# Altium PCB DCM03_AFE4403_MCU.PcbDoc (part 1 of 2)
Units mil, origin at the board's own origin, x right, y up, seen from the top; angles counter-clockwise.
Board outline 608.6 x 413.33 mil, 6 copper layers (Top Layer, Mid-Layer 1, Mid-Layer 2, Mid-Layer 3, Mid-Layer 4, Bottom Layer); 22 components, 39 nets, 207 pads, 99 vias.
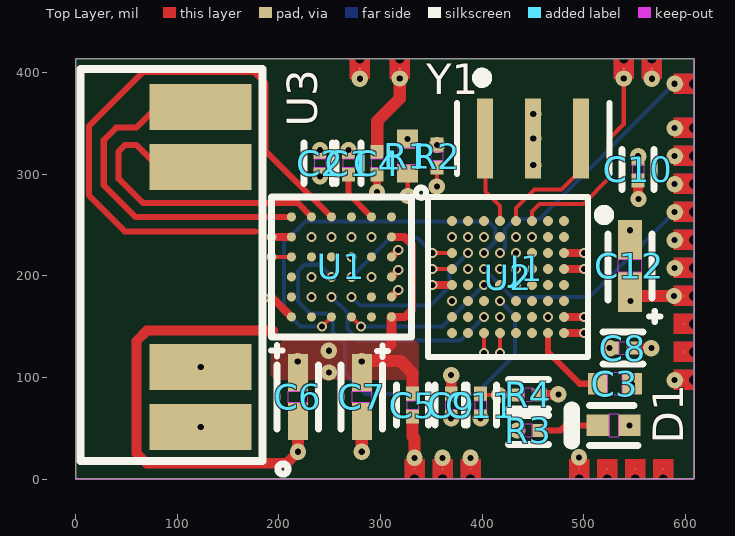
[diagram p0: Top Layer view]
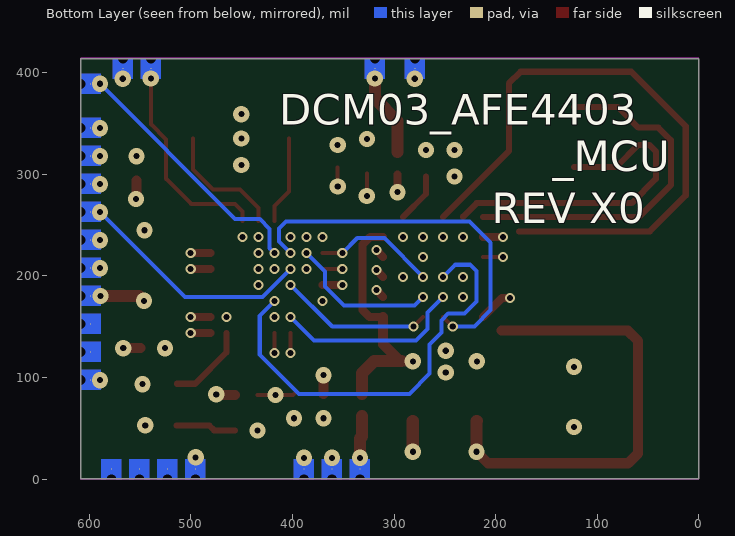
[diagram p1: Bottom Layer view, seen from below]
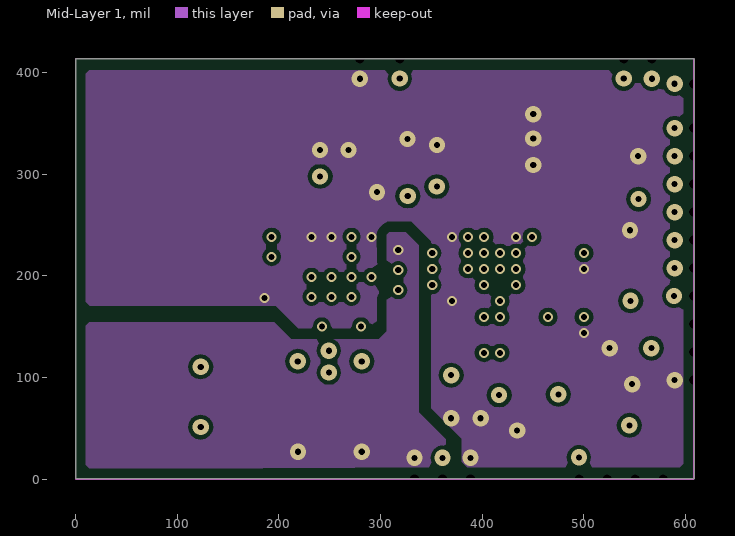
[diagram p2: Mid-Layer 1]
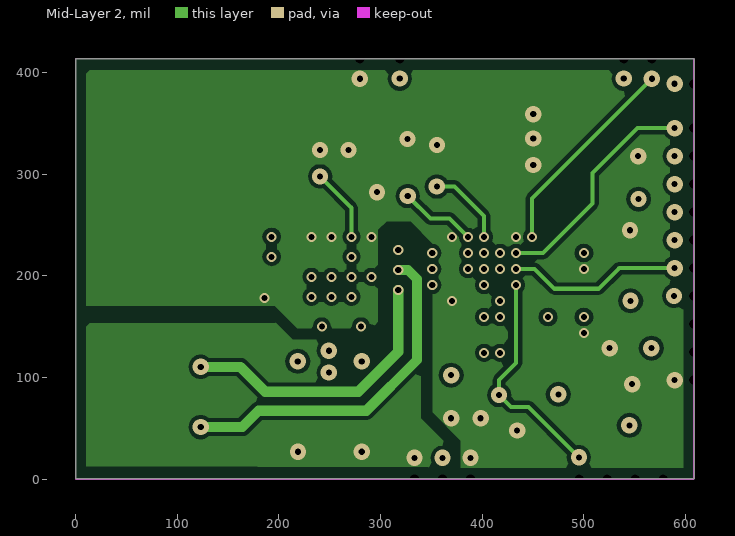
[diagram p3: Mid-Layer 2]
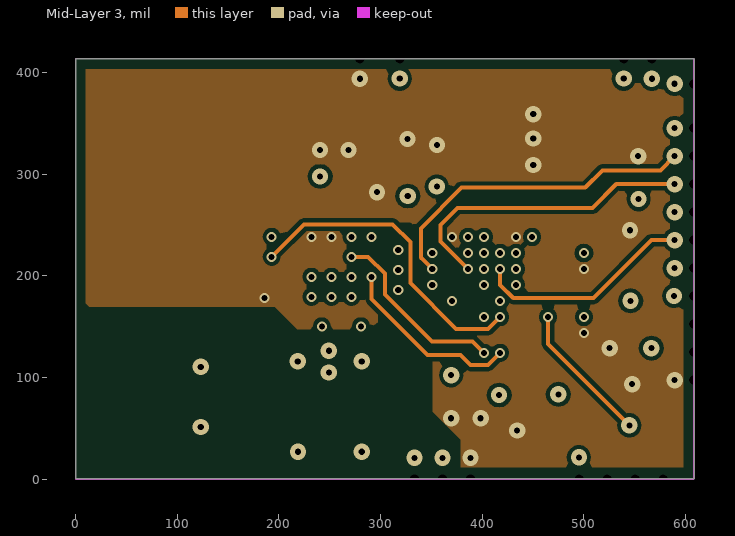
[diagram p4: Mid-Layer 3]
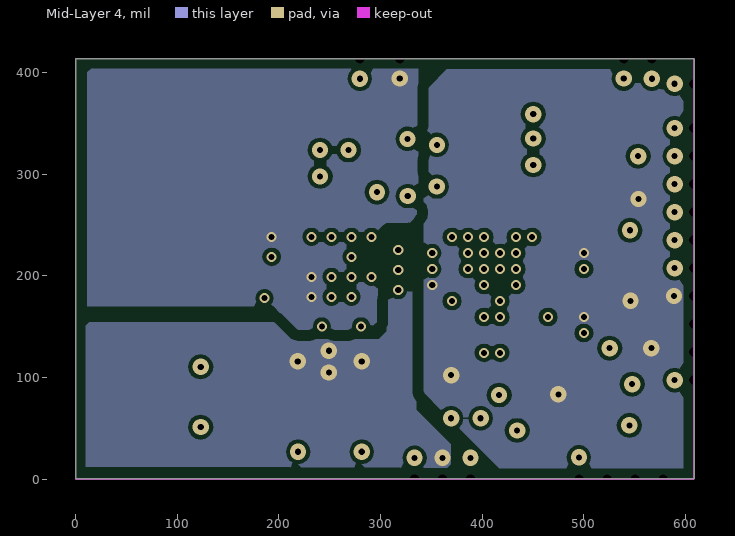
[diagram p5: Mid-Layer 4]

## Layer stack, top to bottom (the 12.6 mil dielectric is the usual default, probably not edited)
Top Layer: signal copper 1.4
Dielectric: dielectric 12.6, FR-4, Dk 4.8
Mid-Layer 1: signal copper 1.4
Dielectric: dielectric 12.6, FR-4, Dk 4.8
Mid-Layer 2: signal copper 1.4
Dielectric: dielectric 12.6, FR-4, Dk 4.8
Mid-Layer 3: signal copper 1.4
Dielectric: dielectric 12.6, FR-4, Dk 4.8
Mid-Layer 4: signal copper 1.4
Dielectric: dielectric 12.6, FR-4, Dk 4.8
Bottom Layer: signal copper 1.4

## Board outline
0,0.62 0,413.95 608.6,413.95 608.6,0.62

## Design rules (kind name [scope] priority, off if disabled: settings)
AcuteAngle [All] p1: minimum=4.50000000000000E+0001 checktracksonly=FALSE
AssemblyTestPointUsage [All] p1: valid=2
Clearance Clearance_1 [inpoly vs inpoly] p1: gap=10
Clearance [All] p2: gap=4
Clearance Clearance_Poly [InPolygon] p3: gap=8
ComponentClearance ComponentClearance_Logo [InComponentClass('Logo')] p1: gap=50 collisioncheckmode=3 verticalgap=10 showdistances=FALSE
ComponentClearance ComponentClearance_ScrewToNut [(HasFootprint('NY PMS 440 0025 PH')) vs (HasFootprint('Keystone_1902C'))] p2: gap=5 collisioncheckmode=3 verticalgap=10 showdistances=FALSE
ComponentClearance ComponentClearance_MountingHoles [InComponentClass('Mounting Holes')] p3: gap=250 collisioncheckmode=3 verticalgap=100000 showdistances=FALSE
ComponentClearance ComponentClearance_SmallPassives [HasFootprint('0201*') or HasFootprint('0402*') or HasFootprint('0508') or HasFootprint('0603*') or HasFootprint('0612') or HasFootprint('0805*') or HasFootprint('0815*') or HasFootprint('0830*') or HasFootprint('1206*') or HasFootprint('1210*') or HasFootprint('1808*') or HasFootprint('1812*') or HasFootprint('1825*') or HasFootprint('2010*') or HasFootprint('2220*') or HasFootprint('2225*') or HasFootprint('2512*') or HasFootprint('2728*') or HasFootprint('3518*') vs HasFootprint('0201*') or HasFootprint('0402*') or HasFootprint('0508') or HasFootprint('0603*') or HasFootprint('0612') or HasFootprint('0805*') or HasFootprint('0815*') or HasFootprint('0830*') or HasFootprint('1206*') or HasFootprint('1210*') or HasFootprint('1808*') or HasFootprint('1812*') or HasFootprint('1825*') or HasFootprint('2010*') or HasFootprint('2220*') or HasFootprint('2225*') or HasFootprint('2512*') or HasFootprint('2728*') or HasFootprint('3518*')] p4: gap=20 collisioncheckmode=3 verticalgap=10 showdistances=FALSE
ComponentClearance ComponentClearance_THtoSMT [IsThruComponent vs IsSMTComponent] p5: gap=100 collisioncheckmode=3 verticalgap=30 showdistances=FALSE
ComponentClearance ComponentClearance_THtoTH [IsThruComponent vs IsThruComponent] p6: gap=118.11 collisioncheckmode=3 verticalgap=30 showdistances=FALSE
ComponentClearance [All] p7: gap=40 collisioncheckmode=3 verticalgap=10 showdistances=FALSE
DiffPairsRouting [All] p1: maxlimit=100 minlimit=10 mostfreqgap=10 maxuncoupledlength=1000
FabricationTestPointUsage TestPointUsage [All] p1: valid=2 allowmultiple=FALSE
FabricationTestpoint Testpoint [All] p1: side=3 testpointundercomponent=TRUE minsize=40 maxsize=100 preferedsize=60 minholesize=0 maxholesize=40 preferedholesize=32 testpointgrid=1 allowsidetop=TRUE allowsidebottom=TRUE usegrid=TRUE gridtolerance=0.01
FanoutControl Fanout_LCC [IsLCC] p1: bgadir=Out bgaviamode=Centered fanoutstyle=Auto fanoutdirection=Alternating viagrid=1 // Fanout_LCC (Default Rule)
FanoutControl Fanout_BGA [IsBGA] p2: bgadir=Out bgaviamode=Centered fanoutstyle=Auto fanoutdirection=Alternating viagrid=1 // Fanout_BGA (Default Rule)
FanoutControl Fanout_Default [All] p4: bgadir=Out bgaviamode=Centered fanoutstyle=Auto fanoutdirection=Alternating viagrid=1 // Fanout_Default (Default Rule)
FanoutControl Fanout_Small [(CompPinCount < 5)] p5: bgadir=Out bgaviamode=Centered fanoutstyle=Auto fanoutdirection=OutThenIn viagrid=1 // Fanout_Small (Default Rule)
HoleSize [All] p1: absolutevalues=TRUE maxlimit=251 minlimit=8 maxpercent=80.000 minpercent=20.000
HoleToHoleClearance [All] p1: gap=9.75 allowstackedmicrovias=TRUE
MinimumAnnularRing MinimumAnnularRing_ThermalPadVias [IsVia and InAnyComponent] p1: minimumring=5.91
MinimumAnnularRing [All] p2: minimumring=9
MinimumSolderMaskSliver MinimumSolderMaskSliver_Logo [InComponentClass('Logo') vs InComponentClass('Logo')] p1: minsoldermaskwidth=0.7
MinimumSolderMaskSliver [All] p2: minsoldermaskwidth=3.94
PlaneClearance [All] p1: clearance=15
PlaneConnect PlaneConnect_1 [isvia] p1: planeconnectstyle=Direct reliefexpansion=20 reliefentries=4 reliefconductorwidth=10 reliefairgap=10
PlaneConnect [All] p2: planeconnectstyle=Relief reliefexpansion=10 reliefentries=4 reliefconductorwidth=10 reliefairgap=10
PolygonConnect [All] p1: connectstyle=Direct reliefconductorwidth=10 reliefentries=4 polygonreliefangle="90 Angle"
RoutingVias ThermalPadVias [IsVia and InAnyComponent] p1: holewidth=7.87 width=19.68 viastyle="Through Hole" minholewidth=7.87 minwidth=19.68 maxholewidth=12.99 maxwidth=23.62
RoutingVias [All] p2: holewidth=16 width=34 viastyle="Through Hole" minholewidth=7.87 minwidth=26 maxholewidth=40 maxwidth=65
SMDToCorner [All] p1: distance=30000
SilkToSilkClearance [All] p1: silktosilkclearance=5
SilkscreenOverComponentPads [All] p1: minsilkscreentomaskgap=5
SolderMaskExpansion [All] p1: expansion=0
Width [All] p1: maxlimit=100 minlimit=4 preferedwidth=10 checkconnectedcopper=TRUE
12 further rules are at their usual default settings.

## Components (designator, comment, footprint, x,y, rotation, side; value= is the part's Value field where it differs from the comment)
C1 "CL03A104KP3NNNC" 0201 268.6,310.95 r90 top locked
C2 "CL03A104KP3NNNC" 0201 240.6,310.95 r90 top locked
C3 "#NAME?" 0402 530.6,93.95 r0 top
C4 "CL03A104KP3NNNC" 0201 296.6,310.95 r270 top locked
C5 "CL03A104KP3NNNC" 0201 331.6,72.95 r270 top locked
C6 "#NAME?" C0603_POL 218.6,80.95 r270 top
C7 "#NAME?" C0603_POL 281.6,80.95 r270 top locked
C8 "CL03A104KP3NNNC" 0201 538.6,128.95 r180 top locked
C9 "CL03A104KP3NNNC" 0201 369.6,72.95 r270 top locked
C10 "CL03A104KP3NNNC" 0201 553.6,304.95 r90 top locked
C11 "GRM033R61A222KA01D" 0201 398.6,72.95 r270 top locked
C12 "#NAME?" C0603_POL1 545.6,209.95 r90 top locked
D1 "PartNumber" LED_0402 529.6,52.95 r0 top locked
J1 "22pin SPO2 Module Connector" CONN-22PADS 608.59,-5.05 r270 top locked
R1 "CRCW04021M00JNED" R0402 326.6,317.95 r270 top
R2 "ERJ-1GE0R00C" R0201 355.6,317.95 r90 top
R3 "RC0603F332CS" R0201 445.6,47.95 r0 top locked
R4 "RC0603F473CS" R0201 445.6,82.95 r0 top locked
U1 "AFE4403" BGA36C50P6X6_304X304X50 261.6,208.95 r270 top locked
U2 "PartNumber" YFF-64 425.6,198.95 r180 top locked
U3 "#NAME?" DCM03 89.6,210.95 r90 top locked
Y1 "PartNumber" RESONATOR-1.3X3.2-MURATA 450.37,335.23 r0 top locked

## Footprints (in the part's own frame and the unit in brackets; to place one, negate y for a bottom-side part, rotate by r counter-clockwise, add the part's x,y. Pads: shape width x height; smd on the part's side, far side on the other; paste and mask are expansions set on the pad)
0201 [mm] "CAP, 0201, 2-PIN"
  rect 0.36x0.32 smd: 1(-0.28,0) 2(0.28,0)
  Top Layer keep-out region: -0.1,-0.15 0.1,-0.15 0.1,0.15 -0.1,0.15
  silkscreen extent -0.5,0.4 0.5,0.4, body extent -0.3,-0.15 0.3,0.15, height 0.33
0402 [mm] "CAP, 0402, 2-PIN"
  rect 0.49x0.54 smd: 1(-0.43,0) 2(0.43,0)
  Top Layer keep-out region: -0.19,-0.27 0.19,-0.27 0.19,0.27 -0.19,0.27
  body extent -0.5,-0.25 0.5,0.25, height 0.56
BGA36C50P6X6_304X304X50 [mm] "BGA, 0.5mm pitch, 6X6, 36 pins"
  round 0.23 smd: A1(-1.25,1.25) A2(-0.75,1.25) A3(-0.25,1.25) A4(0.25,1.25) A5(0.75,1.25) A6(1.25,1.25) B1(-1.25,0.75) B2(-0.75,0.75) B3(-0.25,0.75) B4(0.25,0.75) B5(0.75,0.75) B6(1.25,0.75) C1(-1.25,0.25) C2(-0.75,0.25) C3(-0.25,0.25) C4(0.25,0.25) C5(0.75,0.25) C6(1.25,0.25) D1(-1.25,-0.25) D2(-0.75,-0.25) D3(-0.25,-0.25) D4(0.25,-0.25) D5(0.75,-0.25) D6(1.25,-0.25) E1(-1.25,-0.75) E2(-0.75,-0.75) E3(-0.25,-0.75) E4(0.25,-0.75) E5(0.75,-0.75) E6(1.25,-0.75) F1(-1.25,-1.25) F2(-0.75,-1.25) F3(-0.25,-1.25) F4(0.25,-1.25) F5(0.75,-1.25) F6(1.25,-1.25)
  silkscreen extent -1.98,-1.75 1.75,2.12, body extent -1.52,-1.52 1.52,1.52, height 0.5
C0603_POL [mm] "CAP, TANTALUM, 2-PIN"
  rect 0.95x0.5 smd: 1(-0.6,0) 2(0.6,0)
  Top Layer keep-out region: -0.13,-0.25 0.13,-0.25 0.13,0.25 -0.13,0.25
  silkscreen extent -0.8,-0.52 0.8,0.52, body extent -0.8,-0.43 0.8,0.43, height 0.9
C0603_POL1 [mm] "CAP, TANTULUM, 2-PIN"
  rect 1x0.6 smd: 1(-0.65,0) 2(0.65,0)
  Top Layer keep-out region: -0.15,-0.3 0.15,-0.3 0.15,0.3 -0.15,0.3
  silkscreen extent -0.85,-0.55 0.8,0.55, body extent -0.82,-0.45 0.82,0.45, height 0.9
CONN-22PADS [mil]
  round 0 hole 9.69 mask+0: 0(-419,-69.15) 0(-419,-41.59) 0(-419,-328.99) 0(-419,-289.62) 0(-394.11,0) 0(-350.76,0) 0(-323.2,0) 0(-295.64,0) 0(-268.08,0) 0(-240.52,0) 0(-212.96,0) 0(-185.4,0) 0(-157.84,0) 0(-130.29,0) 0(-102.73,0) 0(-5.01,-30.31) 0(-5.01,-57.87) 0(-5.01,-85.43) 0(-5.01,-112.99) 0(-5.01,-219.87) 0(-5.01,-247.43) 0(-5.01,-274.99)
  rect 1x1 smd: 1(-409.16,-289.62) 2(-409.16,-328.99) 3(-130.28,-9.84) 4(-157.84,-9.84) 5(-14.85,-57.87) 6(-240.52,-9.84) 7(-295.64,-9.84) 8(-323.2,-9.84) 9(-268.08,-9.84) 10(-102.72,-9.84) 11(-14.85,-85.43) 12(-14.85,-30.31) 13(-14.85,-274.99) 14(-14.85,-247.43) 15(-350.76,-9.84) 16(-409.16,-69.15) 17(-14.85,-112.99) 18(-212.96,-9.84) 19(-409.16,-41.59) 20(-394.11,-9.84) 21(-185.4,-9.84) 22(-14.85,-219.87)
  rect 1x1 smd far side: 1(-409.16,-289.62) 2(-409.16,-328.99) 3(-130.28,-9.84) 4(-157.84,-9.84) 5(-14.85,-57.87) 6(-240.52,-9.84) 7(-295.64,-9.84) 8(-323.2,-9.84) 9(-268.08,-9.84) 10(-102.72,-9.84) 11(-14.85,-85.43) 12(-14.85,-30.31) 13(-14.85,-274.99) 14(-14.85,-247.43) 15(-350.76,-9.84) 16(-409.16,-69.15) 17(-14.85,-112.99) 18(-212.96,-9.84) 19(-409.16,-41.59) 20(-394.11,-9.84) 21(-185.4,-9.84) 22(-14.85,-219.87)
  Top Layer region: -5.01,-279.83 -5.01,-284.83 -24.69,-284.83 -24.69,-265.14 -5.01,-265.14 -5.01,-270.14 -5.58,-270.22 -6.23,-270.46 -7.02,-270.83 -7.69,-271.34 -8.28,-271.93 -8.74,-272.68 -9.1,-273.53 -9.27,-274.27 -9.33,-275.1 -9.25,-275.8 -9.09,-276.52 -8.63,-277.48 -8.11,-278.2 -7.4,-278.82 -6.78,-279.19 -6.25,-279.48 -5.71,-279.68 -5.01,-279.83
  Top Layer region: -5.01,-252.27 -5.01,-257.27 -24.69,-257.27 -24.69,-237.59 -5.01,-237.59 -5.01,-242.59 -5.58,-242.66 -6.23,-242.9 -7.02,-243.27 -7.69,-243.78 -8.28,-244.38 -8.74,-245.12 -9.1,-245.97 -9.27,-246.71 -9.33,-247.54 -9.25,-248.24 -9.09,-248.96 -8.63,-249.92 -8.11,-250.64 -7.4,-251.26 -6.78,-251.64 -6.25,-251.92 -5.71,-252.12 -5.01,-252.27
  Top Layer region: -5.01,-224.71 -5.01,-229.71 -24.69,-229.71 -24.69,-210.03 -5.01,-210.03 -5.01,-215.03 -5.58,-215.1 -6.23,-215.34 -7.02,-215.72 -7.69,-216.22 -8.28,-216.82 -8.74,-217.56 -9.1,-218.41 -9.27,-219.15 -9.33,-219.99 -9.25,-220.68 -9.09,-221.4 -8.63,-222.36 -8.11,-223.08 -7.4,-223.7 -6.78,-224.08 -6.25,-224.37 -5.71,-224.56 -5.01,-224.71
  Top Layer region: -5.01,-117.83 -5.01,-122.83 -24.69,-122.83 -24.69,-103.14 -5.01,-103.14 -5.01,-108.14 -5.58,-108.22 -6.23,-108.46 -7.02,-108.83 -7.69,-109.34 -8.28,-109.93 -8.74,-110.68 -9.1,-111.53 -9.27,-112.27 -9.33,-113.1 -9.25,-113.8 -9.09,-114.52 -8.63,-115.48 -8.11,-116.2 -7.4,-116.82 -6.78,-117.19 -6.25,-117.48 -5.71,-117.68 -5.01,-117.83
  Top Layer region: -5.01,-90.27 -5.01,-95.27 -24.69,-95.27 -24.69,-75.59 -5.01,-75.59 -5.01,-80.59 -5.58,-80.66 -6.23,-80.9 -7.02,-81.27 -7.69,-81.78 -8.28,-82.38 -8.74,-83.12 -9.1,-83.97 -9.27,-84.71 -9.33,-85.54 -9.25,-86.24 -9.09,-86.96 -8.63,-87.92 -8.11,-88.64 -7.4,-89.26 -6.78,-89.64 -6.25,-89.92 -5.71,-90.12 -5.01,-90.27
  Top Layer region: -5.01,-62.71 -5.01,-67.71 -24.69,-67.71 -24.69,-48.03 -5.01,-48.03 -5.01,-53.03 -5.58,-53.1 -6.23,-53.34 -7.02,-53.72 -7.69,-54.22 -8.28,-54.82 -8.74,-55.56 -9.1,-56.41 -9.27,-57.15 -9.33,-57.99 -9.25,-58.68 -9.09,-59.4 -8.63,-60.36 -8.11,-61.08 -7.4,-61.7 -6.78,-62.08 -6.25,-62.37 -5.71,-62.56 -5.01,-62.71
  Top Layer region: -5.01,-35.15 -5.01,-40.15 -24.69,-40.15 -24.69,-20.47 -5.01,-20.47 -5.01,-25.47 -5.58,-25.55 -6.23,-25.78 -7.02,-26.16 -7.69,-26.66 -8.28,-27.26 -8.74,-28 -9.1,-28.85 -9.27,-29.59 -9.33,-30.43 -9.25,-31.12 -9.09,-31.84 -8.63,-32.8 -8.11,-33.52 -7.4,-34.14 -6.78,-34.52 -6.25,-34.81 -5.71,-35 -5.01,-35.15
  Top Layer region: -97.88,0 -92.88,0 -92.88,-19.68 -112.57,-19.68 -112.57,0 -107.57,0 -107.49,-0.57 -107.26,-1.22 -106.88,-2.01 -106.38,-2.68 -105.78,-3.27 -105.04,-3.73 -104.19,-4.09 -103.44,-4.26 -102.61,-4.32 -101.92,-4.24 -101.2,-4.08 -100.23,-3.62 -99.52,-3.1 -98.9,-2.39 -98.52,-1.77 -98.23,-1.24 -98.03,-0.7 -97.89,0
  Top Layer region: -125.44,0 -120.44,0 -120.44,-19.68 -140.13,-19.68 -140.13,0 -135.13,0 -135.05,-0.57 -134.82,-1.22 -134.44,-2.01 -133.94,-2.68 -133.34,-3.27 -132.59,-3.73 -131.74,-4.09 -131,-4.26 -130.17,-4.32 -129.48,-4.24 -128.76,-4.08 -127.79,-3.62 -127.08,-3.1 -126.46,-2.39 -126.08,-1.77 -125.79,-1.24 -125.59,-0.7 -125.45,0
  Top Layer region: -153,0 -148,0 -148,-19.68 -167.69,-19.68 -167.69,0 -162.69,0 -162.61,-0.57 -162.38,-1.22 -162,-2.01 -161.5,-2.68 -160.9,-3.27 -160.15,-3.73 -159.3,-4.09 -158.56,-4.26 -157.73,-4.32 -157.04,-4.24 -156.32,-4.08 -155.35,-3.62 -154.64,-3.1 -154.02,-2.39 -153.64,-1.77 -153.35,-1.24 -153.15,-0.7 -153.01,0
  Top Layer region: -180.56,0 -175.56,0 -175.56,-19.68 -195.25,-19.68 -195.25,0 -190.25,0 -190.17,-0.57 -189.94,-1.22 -189.56,-2.01 -189.05,-2.68 -188.46,-3.27 -187.71,-3.73 -186.86,-4.09 -186.12,-4.26 -185.29,-4.32 -184.6,-4.24 -183.87,-4.08 -182.91,-3.62 -182.19,-3.1 -181.57,-2.39 -181.2,-1.77 -180.91,-1.24 -180.71,-0.7 -180.56,0
  Top Layer region: -208.12,0 -203.12,0 -203.12,-19.68 -222.81,-19.68 -222.81,0 -217.81,0 -217.73,-0.57 -217.49,-1.22 -217.12,-2.01 -216.61,-2.68 -216.02,-3.27 -215.27,-3.73 -214.42,-4.09 -213.68,-4.26 -212.85,-4.32 -212.15,-4.24 -211.43,-4.08 -210.47,-3.62 -209.75,-3.1 -209.13,-2.39 -208.76,-1.77 -208.47,-1.24 -208.27,-0.7 -208.12,0
  Top Layer region: -235.68,0 -230.68,0 -230.68,-19.68 -250.36,-19.68 -250.36,0 -245.36,0 -245.29,-0.57 -245.05,-1.22 -244.68,-2.01 -244.17,-2.68 -243.57,-3.27 -242.83,-3.73 -241.98,-4.09 -241.24,-4.26 -240.41,-4.32 -239.71,-4.24 -238.99,-4.08 -238.03,-3.62 -237.31,-3.1 -236.69,-2.39 -236.31,-1.77 -236.03,-1.24 -235.83,-0.7 -235.68,0
  Top Layer region: -263.24,0 -258.24,0 -258.24,-19.68 -277.92,-19.68 -277.92,0 -272.92,0 -272.85,-0.57 -272.61,-1.22 -272.23,-2.01 -271.73,-2.68 -271.13,-3.27 -270.39,-3.73 -269.54,-4.09 -268.8,-4.26 -267.96,-4.32 -267.27,-4.24 -266.55,-4.08 -265.59,-3.62 -264.87,-3.1 -264.25,-2.39 -263.87,-1.77 -263.58,-1.24 -263.39,-0.7 -263.24,0
  Top Layer region: -290.8,0 -285.8,0 -285.8,-19.68 -305.48,-19.68 -305.48,0 -300.48,0 -300.4,-0.57 -300.17,-1.22 -299.79,-2.01 -299.29,-2.68 -298.69,-3.27 -297.95,-3.73 -297.1,-4.09 -296.36,-4.26 -295.52,-4.32 -294.83,-4.24 -294.11,-4.08 -293.15,-3.62 -292.43,-3.1 -291.81,-2.39 -291.43,-1.77 -291.14,-1.24 -290.95,-0.7 -290.8,0
  Top Layer region: -318.36,0 -313.36,0 -313.36,-19.68 -333.04,-19.68 -333.04,0 -328.04,0 -327.96,-0.57 -327.73,-1.22 -327.35,-2.01 -326.85,-2.68 -326.25,-3.27 -325.51,-3.73 -324.66,-4.09 -323.92,-4.26 -323.08,-4.32 -322.39,-4.24 -321.67,-4.08 -320.71,-3.62 -319.99,-3.1 -319.37,-2.39 -318.99,-1.77 -318.7,-1.24 -318.51,-0.7 -318.36,0
  Top Layer region: -345.92,0 -340.92,0 -340.92,-19.68 -360.6,-19.68 -360.6,0 -355.6,0 -355.52,-0.57 -355.29,-1.22 -354.91,-2.01 -354.41,-2.68 -353.81,-3.27 -353.07,-3.73 -352.22,-4.09 -351.48,-4.26 -350.64,-4.32 -349.95,-4.24 -349.23,-4.08 -348.27,-3.62 -347.55,-3.1 -346.93,-2.39 -346.55,-1.77 -346.26,-1.24 -346.06,-0.7 -345.92,0
  Top Layer region: -389.27,0 -384.27,0 -384.27,-19.68 -403.96,-19.68 -403.96,0 -398.96,0 -398.88,-0.57 -398.64,-1.22 -398.27,-2.01 -397.76,-2.68 -397.17,-3.27 -396.42,-3.73 -395.57,-4.09 -394.83,-4.26 -394,-4.32 -393.3,-4.24 -392.58,-4.08 -391.62,-3.62 -390.9,-3.1 -390.28,-2.39 -389.91,-1.77 -389.62,-1.24 -389.42,-0.7 -389.27,0
  Top Layer region: -419,-36.75 -419,-31.75 -399.32,-31.75 -399.32,-51.43 -419,-51.43 -419,-46.43 -418.43,-46.35 -417.78,-46.12 -416.99,-45.74 -416.32,-45.24 -415.73,-44.64 -415.27,-43.9 -414.91,-43.05 -414.74,-42.31 -414.68,-41.47 -414.76,-40.78 -414.92,-40.06 -415.38,-39.1 -415.9,-38.38 -416.61,-37.76 -417.23,-37.38 -417.76,-37.09 -418.3,-36.9 -419,-36.75
  Top Layer region: -419,-64.31 -419,-59.31 -399.32,-59.31 -399.32,-78.99 -419,-78.99 -419,-73.99 -418.43,-73.91 -417.78,-73.68 -416.99,-73.3 -416.32,-72.8 -415.73,-72.2 -415.27,-71.46 -414.91,-70.61 -414.74,-69.87 -414.68,-69.03 -414.76,-68.34 -414.92,-67.62 -415.38,-66.66 -415.9,-65.94 -416.61,-65.32 -417.23,-64.94 -417.76,-64.65 -418.3,-64.46 -419,-64.31
  Top Layer region: -419,-284.78 -419,-279.78 -399.32,-279.78 -399.32,-299.46 -419,-299.46 -419,-294.46 -418.43,-294.39 -417.78,-294.15 -416.99,-293.78 -416.32,-293.27 -415.73,-292.67 -415.27,-291.93 -414.91,-291.08 -414.74,-290.34 -414.68,-289.51 -414.76,-288.81 -414.92,-288.09 -415.38,-287.13 -415.9,-286.41 -416.61,-285.79 -417.23,-285.41 -417.76,-285.13 -418.3,-284.93 -419,-284.78
  Top Layer region: -419,-324.15 -419,-319.15 -399.32,-319.15 -399.32,-338.83 -419,-338.83 -419,-333.83 -418.43,-333.76 -417.78,-333.52 -416.99,-333.15 -416.32,-332.64 -415.73,-332.04 -415.27,-331.3 -414.91,-330.45 -414.74,-329.71 -414.68,-328.88 -414.76,-328.18 -414.92,-327.46 -415.38,-326.5 -415.9,-325.78 -416.61,-325.16 -417.23,-324.78 -417.76,-324.5 -418.3,-324.3 -419,-324.15
  Bottom Layer region: -419,-324.15 -419,-319.15 -399.32,-319.15 -399.32,-338.83 -419,-338.83 -419,-333.83 -418.43,-333.76 -417.78,-333.52 -416.99,-333.15 -416.32,-332.64 -415.73,-332.04 -415.27,-331.3 -414.91,-330.45 -414.74,-329.71 -414.68,-328.88 -414.76,-328.18 -414.92,-327.46 -415.38,-326.5 -415.9,-325.78 -416.61,-325.16 -417.23,-324.78 -417.76,-324.5 -418.3,-324.3 -419,-324.15
  Bottom Layer region: -419,-284.78 -419,-279.78 -399.32,-279.78 -399.32,-299.46 -419,-299.46 -419,-294.46 -418.43,-294.39 -417.78,-294.15 -416.99,-293.78 -416.32,-293.27 -415.73,-292.67 -415.27,-291.93 -414.91,-291.08 -414.74,-290.34 -414.68,-289.51 -414.76,-288.81 -414.92,-288.09 -415.38,-287.13 -415.9,-286.41 -416.61,-285.79 -417.23,-285.41 -417.76,-285.13 -418.3,-284.93 -419,-284.78
  Bottom Layer region: -419,-64.31 -419,-59.31 -399.32,-59.31 -399.32,-78.99 -419,-78.99 -419,-73.99 -418.43,-73.91 -417.78,-73.68 -416.99,-73.3 -416.32,-72.8 -415.73,-72.2 -415.27,-71.46 -414.91,-70.61 -414.74,-69.87 -414.68,-69.03 -414.76,-68.34 -414.92,-67.62 -415.38,-66.66 -415.9,-65.94 -416.61,-65.32 -417.23,-64.94 -417.76,-64.65 -418.3,-64.46 -419,-64.31
  Bottom Layer region: -419,-36.75 -419,-31.75 -399.32,-31.75 -399.32,-51.43 -419,-51.43 -419,-46.43 -418.43,-46.35 -417.78,-46.12 -416.99,-45.74 -416.32,-45.24 -415.73,-44.64 -415.27,-43.9 -414.91,-43.05 -414.74,-42.31 -414.68,-41.47 -414.76,-40.78 -414.92,-40.06 -415.38,-39.1 -415.9,-38.38 -416.61,-37.76 -417.23,-37.38 -417.76,-37.09 -418.3,-36.9 -419,-36.75
  Bottom Layer region: -389.27,0 -384.27,0 -384.27,-19.68 -403.96,-19.68 -403.96,0 -398.96,0 -398.88,-0.57 -398.64,-1.22 -398.27,-2.01 -397.76,-2.68 -397.17,-3.27 -396.42,-3.73 -395.57,-4.09 -394.83,-4.26 -394,-4.32 -393.3,-4.24 -392.58,-4.08 -391.62,-3.62 -390.9,-3.1 -390.28,-2.39 -389.91,-1.77 -389.62,-1.24 -389.42,-0.7 -389.27,0
  Bottom Layer region: -345.92,0 -340.92,0 -340.92,-19.68 -360.6,-19.68 -360.6,0 -355.6,0 -355.52,-0.57 -355.29,-1.22 -354.91,-2.01 -354.41,-2.68 -353.81,-3.27 -353.07,-3.73 -352.22,-4.09 -351.48,-4.26 -350.64,-4.32 -349.95,-4.24 -349.23,-4.08 -348.27,-3.62 -347.55,-3.1 -346.93,-2.39 -346.55,-1.77 -346.26,-1.24 -346.06,-0.7 -345.92,0
  Bottom Layer region: -318.36,0 -313.36,0 -313.36,-19.68 -333.04,-19.68 -333.04,0 -328.04,0 -327.96,-0.57 -327.73,-1.22 -327.35,-2.01 -326.85,-2.68 -326.25,-3.27 -325.51,-3.73 -324.66,-4.09 -323.92,-4.26 -323.08,-4.32 -322.39,-4.24 -321.67,-4.08 -320.71,-3.62 -319.99,-3.1 -319.37,-2.39 -318.99,-1.77 -318.7,-1.24 -318.51,-0.7 -318.36,0
  Bottom Layer region: -290.8,0 -285.8,0 -285.8,-19.68 -305.48,-19.68 -305.48,0 -300.48,0 -300.4,-0.57 -300.17,-1.22 -299.79,-2.01 -299.29,-2.68 -298.69,-3.27 -297.95,-3.73 -297.1,-4.09 -296.36,-4.26 -295.52,-4.32 -294.83,-4.24 -294.11,-4.08 -293.15,-3.62 -292.43,-3.1 -291.81,-2.39 -291.43,-1.77 -291.14,-1.24 -290.95,-0.7 -290.8,0
  Bottom Layer region: -263.24,0 -258.24,0 -258.24,-19.68 -277.92,-19.68 -277.92,0 -272.92,0 -272.85,-0.57 -272.61,-1.22 -272.23,-2.01 -271.73,-2.68 -271.13,-3.27 -270.39,-3.73 -269.54,-4.09 -268.8,-4.26 -267.96,-4.32 -267.27,-4.24 -266.55,-4.08 -265.59,-3.62 -264.87,-3.1 -264.25,-2.39 -263.87,-1.77 -263.58,-1.24 -263.39,-0.7 -263.24,0
  Bottom Layer region: -235.68,0 -230.68,0 -230.68,-19.68 -250.36,-19.68 -250.36,0 -245.36,0 -245.29,-0.57 -245.05,-1.22 -244.68,-2.01 -244.17,-2.68 -243.57,-3.27 -242.83,-3.73 -241.98,-4.09 -241.24,-4.26 -240.41,-4.32 -239.71,-4.24 -238.99,-4.08 -238.03,-3.62 -237.31,-3.1 -236.69,-2.39 -236.31,-1.77 -236.03,-1.24 -235.83,-0.7 -235.68,0
  Bottom Layer region: -208.12,0 -203.12,0 -203.12,-19.68 -222.81,-19.68 -222.81,0 -217.81,0 -217.73,-0.57 -217.49,-1.22 -217.12,-2.01 -216.61,-2.68 -216.02,-3.27 -215.27,-3.73 -214.42,-4.09 -213.68,-4.26 -212.85,-4.32 -212.15,-4.24 -211.43,-4.08 -210.47,-3.62 -209.75,-3.1 -209.13,-2.39 -208.76,-1.77 -208.47,-1.24 -208.27,-0.7 -208.12,0
  Bottom Layer region: -180.56,0 -175.56,0 -175.56,-19.68 -195.25,-19.68 -195.25,0 -190.25,0 -190.17,-0.57 -189.94,-1.22 -189.56,-2.01 -189.05,-2.68 -188.46,-3.27 -187.71,-3.73 -186.86,-4.09 -186.12,-4.26 -185.29,-4.32 -184.6,-4.24 -183.87,-4.08 -182.91,-3.62 -182.19,-3.1 -181.57,-2.39 -181.2,-1.77 -180.91,-1.24 -180.71,-0.7 -180.56,0
  Bottom Layer region: -153,0 -148,0 -148,-19.68 -167.69,-19.68 -167.69,0 -162.69,0 -162.61,-0.57 -162.38,-1.22 -162,-2.01 -161.5,-2.68 -160.9,-3.27 -160.15,-3.73 -159.3,-4.09 -158.56,-4.26 -157.73,-4.32 -157.04,-4.24 -156.32,-4.08 -155.35,-3.62 -154.64,-3.1 -154.02,-2.39 -153.64,-1.77 -153.35,-1.24 -153.15,-0.7 -153.01,0
  Bottom Layer region: -125.44,0 -120.44,0 -120.44,-19.68 -140.13,-19.68 -140.13,0 -135.13,0 -135.05,-0.57 -134.82,-1.22 -134.44,-2.01 -133.94,-2.68 -133.34,-3.27 -132.59,-3.73 -131.74,-4.09 -131,-4.26 -130.17,-4.32 -129.48,-4.24 -128.76,-4.08 -127.79,-3.62 -127.08,-3.1 -126.46,-2.39 -126.08,-1.77 -125.79,-1.24 -125.59,-0.7 -125.45,0
  Bottom Layer region: -97.88,0 -92.88,0 -92.88,-19.68 -112.57,-19.68 -112.57,0 -107.57,0 -107.49,-0.57 -107.26,-1.22 -106.88,-2.01 -106.38,-2.68 -105.78,-3.27 -105.04,-3.73 -104.19,-4.09 -103.44,-4.26 -102.61,-4.32 -101.92,-4.24 -101.2,-4.08 -100.23,-3.62 -99.52,-3.1 -98.9,-2.39 -98.52,-1.77 -98.23,-1.24 -98.03,-0.7 -97.89,0
  Bottom Layer region: -5.01,-35.15 -5.01,-40.15 -24.69,-40.15 -24.69,-20.47 -5.01,-20.47 -5.01,-25.47 -5.58,-25.55 -6.23,-25.78 -7.02,-26.16 -7.69,-26.66 -8.28,-27.26 -8.74,-28 -9.1,-28.85 -9.27,-29.59 -9.33,-30.43 -9.25,-31.12 -9.09,-31.84 -8.63,-32.8 -8.11,-33.52 -7.4,-34.14 -6.78,-34.52 -6.25,-34.81 -5.71,-35 -5.01,-35.15
  Bottom Layer region: -5.01,-62.71 -5.01,-67.71 -24.69,-67.71 -24.69,-48.03 -5.01,-48.03 -5.01,-53.03 -5.58,-53.1 -6.23,-53.34 -7.02,-53.72 -7.69,-54.22 -8.28,-54.82 -8.74,-55.56 -9.1,-56.41 -9.27,-57.15 -9.33,-57.99 -9.25,-58.68 -9.09,-59.4 -8.63,-60.36 -8.11,-61.08 -7.4,-61.7 -6.78,-62.08 -6.25,-62.37 -5.71,-62.56 -5.01,-62.71
  Bottom Layer region: -5.01,-90.27 -5.01,-95.27 -24.69,-95.27 -24.69,-75.59 -5.01,-75.59 -5.01,-80.59 -5.58,-80.66 -6.23,-80.9 -7.02,-81.27 -7.69,-81.78 -8.28,-82.38 -8.74,-83.12 -9.1,-83.97 -9.27,-84.71 -9.33,-85.54 -9.25,-86.24 -9.09,-86.96 -8.63,-87.92 -8.11,-88.64 -7.4,-89.26 -6.78,-89.64 -6.25,-89.92 -5.71,-90.12 -5.01,-90.27
  Bottom Layer region: -5.01,-117.83 -5.01,-122.83 -24.69,-122.83 -24.69,-103.14 -5.01,-103.14 -5.01,-108.14 -5.58,-108.22 -6.23,-108.46 -7.02,-108.83 -7.69,-109.34 -8.28,-109.93 -8.74,-110.68 -9.1,-111.53 -9.27,-112.27 -9.33,-113.1 -9.25,-113.8 -9.09,-114.52 -8.63,-115.48 -8.11,-116.2 -7.4,-116.82 -6.78,-117.19 -6.25,-117.48 -5.71,-117.68 -5.01,-117.83
  Bottom Layer region: -5.01,-224.71 -5.01,-229.71 -24.69,-229.71 -24.69,-210.03 -5.01,-210.03 -5.01,-215.03 -5.58,-215.1 -6.23,-215.34 -7.02,-215.72 -7.69,-216.22 -8.28,-216.82 -8.74,-217.56 -9.1,-218.41 -9.27,-219.15 -9.33,-219.99 -9.25,-220.68 -9.09,-221.4 -8.63,-222.36 -8.11,-223.08 -7.4,-223.7 -6.78,-224.08 -6.25,-224.37 -5.71,-224.56 -5.01,-224.71
  Bottom Layer region: -5.01,-252.27 -5.01,-257.27 -24.69,-257.27 -24.69,-237.59 -5.01,-237.59 -5.01,-242.59 -5.58,-242.66 -6.23,-242.9 -7.02,-243.27 -7.69,-243.78 -8.28,-244.38 -8.74,-245.12 -9.1,-245.97 -9.27,-246.71 -9.33,-247.54 -9.25,-248.24 -9.09,-248.96 -8.63,-249.92 -8.11,-250.64 -7.4,-251.26 -6.78,-251.64 -6.25,-251.92 -5.71,-252.12 -5.01,-252.27
  Bottom Layer region: -5.01,-279.83 -5.01,-284.83 -24.69,-284.83 -24.69,-265.14 -5.01,-265.14 -5.01,-270.14 -5.58,-270.22 -6.23,-270.46 -7.02,-270.83 -7.69,-271.34 -8.28,-271.93 -8.74,-272.68 -9.1,-273.53 -9.27,-274.27 -9.33,-275.1 -9.25,-275.8 -9.09,-276.52 -8.63,-277.48 -8.11,-278.2 -7.4,-278.82 -6.78,-279.19 -6.25,-279.48 -5.71,-279.68 -5.01,-279.83
DCM03 [mm] "Integrated Dual Emitter and Photodetector; 4 Leads"
  rect 1.15x2.55 smd: 1(-4.056,-0.85) 2(-2.55,-0.85) 3(2.45,-0.85) 4(3.95,-0.85)
  silkscreen extent -5.23,-3.03 4.9,2.15
LED_0402 [mm] "LED, CHIP, 2PIN"
  rect 0.57x0.54 smd: A(0.39,0) K(-0.39,0)
  Top Layer keep-out region: -0.12,-0.28 0.12,-0.28 0.12,0.28 -0.12,0.28
  silkscreen extent -1.05,-0.5 0.6,0.5, body extent -0.5,-0.25 0.5,0.25, height 0.6
R0201 [mm] "RES, 0201, 2-PIN"
  rect 0.36x0.32 smd: 1(-0.28,0) 2(0.28,0)
  Top Layer keep-out region: -0.1,-0.16 0.1,-0.16 0.1,0.16 -0.1,0.16
  body extent -0.3,-0.15 0.3,0.15, height 0.3
R0402 [mm] "RES, 0402, 2-PIN"
  rect 0.47x0.52 smd: 1(-0.43,0) 2(0.43,0)
  Top Layer keep-out region: -0.2,-0.25 0.2,-0.25 0.2,0.25 -0.2,0.25
  body extent -0.5,-0.25 0.5,0.25, height 0.4
RESONATOR-1.3X3.2-MURATA [mm]
  rect 0.4x2 smd: 1(-1.2,0) 2(0,0) 3(1.2,0)
  silkscreen extent -1.91,-0.89 1.91,1.65
YFF-64 [mm]
  round 0.25 smd: A1(-1.4,-1.4) A2(-1.4,-1) A3(-1.4,-0.6) A4(-1.4,-0.2) A5(-1.4,0.2) A6(-1.4,0.6) A7(-1.4,1) A8(-1.4,1.4) B1(-1,-1.4) B2(-1,-1) B3(-1,-0.6) B4(-1,-0.2) B5(-1,0.2) B6(-1,0.6) B7(-1,1) B8(-1,1.4) C1(-0.6,-1.4) C2(-0.6,-1) C3(-0.6,-0.6) C4(-0.6,-0.2) C5(-0.6,0.2) C6(-0.6,0.6) C7(-0.6,1) C8(-0.6,1.4) D1(-0.2,-1.4) D2(-0.2,-1) D3(-0.2,-0.6) D4(-0.2,-0.2) D5(-0.2,0.2) D6(-0.2,0.6) D7(-0.2,1) D8(-0.2,1.4) E1(0.2,-1.4) E2(0.2,-1) E3(0.2,-0.6) E4(0.2,-0.2) E5(0.2,0.2) E6(0.2,0.6) E7(0.2,1) E8(0.2,1.4) F1(0.6,-1.4) F2(0.6,-1) F3(0.6,-0.6) F4(0.6,-0.2) F5(0.6,0.2) F6(0.6,0.6) F7(0.6,1) F8(0.6,1.4) G1(1,-1.4) G2(1,-1) G3(1,-0.6) G4(1,-0.2) G5(1,0.2) G6(1,0.6) G7(1,1) G8(1,1.4) H1(1.4,-1.4) H2(1.4,-1) H3(1.4,-0.6) H4(1.4,-0.2) H5(1.4,0.2) H6(1.4,0.6) H7(1.4,1) H8(1.4,1.4)
  silkscreen extent -2.52,-2 2,2

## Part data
C1 C2 C4 C5 C8 C9 C10: "CAP, CERM, 0.1uF, 10V, +/-10%, X5R, 0201"
C3: library part C1005X5R1C474K, "CAP, CERAMIC, 470nF, 10%, 16V, X5R, 0402"
C6: library part TCM1A225M8R, "CAP, TANTALUM, 2.2uF, 20%, 10V, 0603"
C7: library part F980J106MMA, "CAP,TANTALUM, 33uF, 20%, 6.3V, 1.5 OHM, 0603"
C11: "CAP, CERM, 2200pF, 10V, +/-10%, X5R, 0201"
C12: library part F980J106MMA, "CAP,TANTALUM, 10UF, 20%, 6.3V, 6 OHM, SMT0603"
D1: library part APHHS1005CGCK, "LED, GREEN, SMT0402"
J1: library part Conn-22pin-PadsOnly, "22pin SPO2 Module Connector pads"
R1: "RES, 1.0Meg ohm, 5%, 0.063W, 0402"
R2: "RES, 0 ohm, 5%, 0.05W, 0201"
R3: library part ERJ-1GEF49R9C, "RES, 3.3k ohm, 1%, 0.05W, 0201"
R4: library part ERJ-1GEF49R9C, "RES, 47k ohm, 1%, 0.05W, 0201"
U1: "BGA, 36 PINS"
U2: library part MSP430F5528IYFFR, "IC, MIXED SIGNAL MICROCONTROLLER, BGA-64"
U3: library part DCM03, "Integrated Dual Emitter and Photodetector"
Y1: library part CSTCE8M00G55-R0, "CRYSTAL, PIEZO CERAMIC RESONATOR, 16.00 MHz, SMD, 0.5%, 15pF, SMD"

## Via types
v1: diameter 16, hole 6, Top Layer to Bottom Layer, 50 vias
v2: diameter 10, hole 6, Top Layer to Bottom Layer, 49 vias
